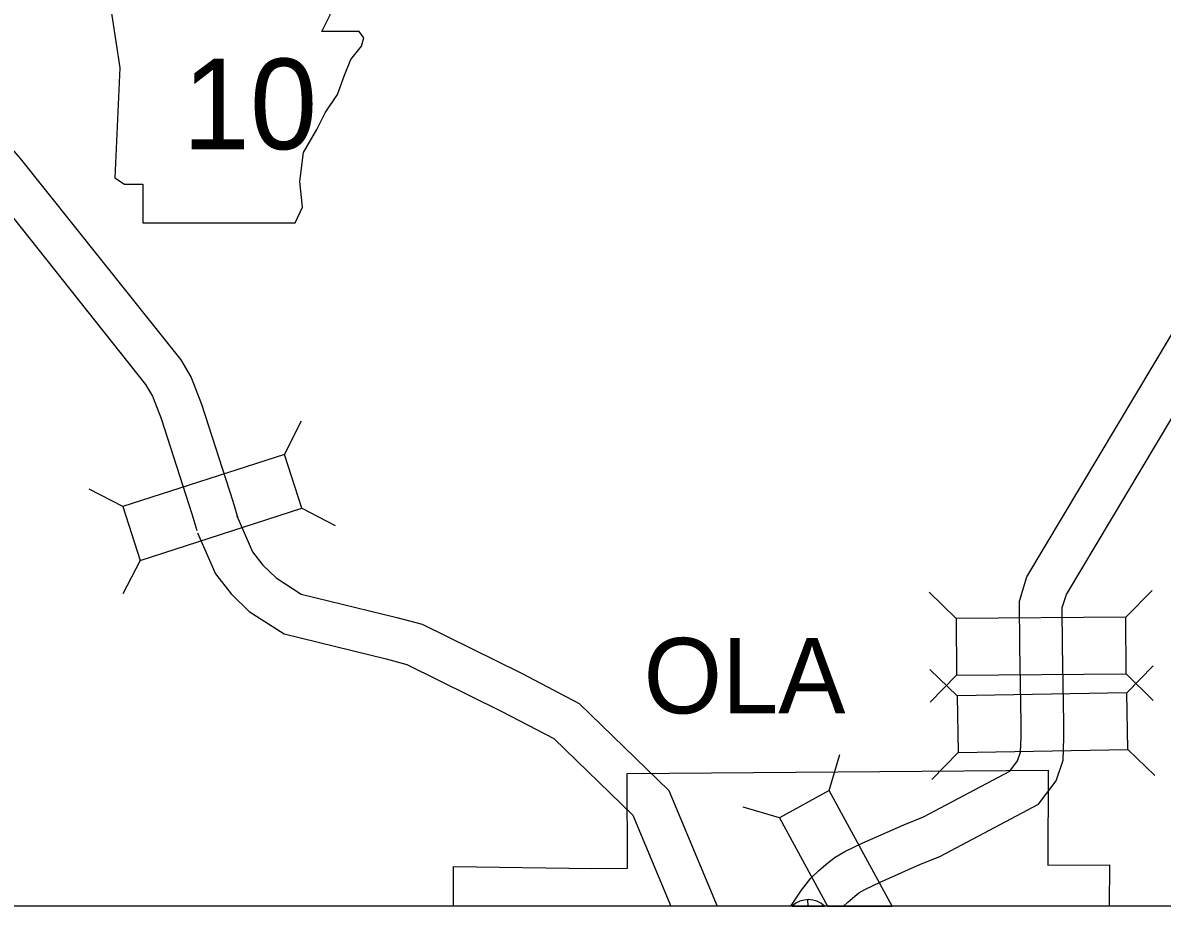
# Model space of a CAD drawing. Extents: x 1374139 to 1377472, y 1168351 to 1170484.
# Drawn here: x 1374355.8 to 1374435.6, y 1169604.3 to 1169666.1 of the extents above; entities that cross this region are included whole.
import ezdxf

# ---------------------------------------------------------------- set-up
doc = ezdxf.new("R2010")
doc.units = 0
doc.layers.add('26', color=7, linetype='Continuous')
doc.layers.add('Default', color=7, linetype='Continuous')

msp = doc.modelspace()

# ---------------------------------------------------------------- linework, layer by layer
at = {"layer": '26'}
msp.add_lwpolyline([(1374299.152, 1170388.771), (1375028.549, 1170388.771), (1375028.549, 1169604.285), (1374299.152, 1169604.285)], close=True, dxfattribs=at)
at = {"layer": 'Default'}
for p, q in [((1374374.148, 1169635.887), (1374375.352, 1169638.236)), ((1374362.84, 1169632.244), (1374360.491, 1169633.448)), ((1374375.362, 1169632.118), (1374377.712, 1169630.913)), ((1374364.055, 1169628.475), (1374362.85, 1169626.126)), ((1374421.143, 1169624.407), (1374419.263, 1169626.26)), ((1374433.023, 1169624.497), (1374434.876, 1169626.378)), ((1374433.095, 1169619.21), (1374434.93, 1169621.108)), ((1374421.217, 1169619.005), (1374419.318, 1169620.84)), ((1374421.173, 1169620.448), (1374419.321, 1169618.567)), ((1374433.053, 1169620.537), (1374434.934, 1169618.685)), ((1374412.26, 1169612.369), (1374413.005, 1169614.902)), ((1374421.285, 1169615.046), (1374419.451, 1169613.147)), ((1374433.163, 1169615.25), (1374435.062, 1169613.416)), ((1374398.137, 1169613.561), (1374427.592, 1169613.812)), ((1374427.592, 1169613.812), (1374427.573, 1169607.151)), ((1374398.164, 1169606.951), (1374398.137, 1169613.561)), ((1374412.26, 1169612.369), (1374408.784, 1169610.473)), ((1374416.67, 1169604.285), (1374412.26, 1169612.369)), ((1374408.784, 1169610.473), (1374406.251, 1169611.218)), ((1374408.784, 1169610.473), (1374412.159, 1169604.285)), ((1374385.975, 1169604.285), (1374385.973, 1169607.06)), ((1374385.973, 1169607.06), (1374395.653, 1169606.916)), ((1374395.653, 1169606.916), (1374398.164, 1169606.951)), ((1374427.573, 1169607.151), (1374431.884, 1169607.17)), ((1374431.884, 1169607.17), (1374431.86, 1169604.285)), ((1374431.86, 1169604.285), (1374385.975, 1169604.285)), ((1374409.68, 1169604.285), (1374411.945, 1169604.285)), ((1374410.786, 1169604.285), (1374410.775, 1169604.743)), ((1374412.159, 1169604.285), (1374416.67, 1169604.285))]:
    msp.add_line(p, q, dxfattribs=at)
for points in [[(1374361.873, 1169667.995), (1374362.634, 1169662.92), (1374362.296, 1169655.222), (1374362.973, 1169654.799), (1374364.242, 1169654.799), (1374364.242, 1169652.092), (1374374.9, 1169652.092), (1374375.407, 1169653.192), (1374375.238, 1169654.968), (1374375.492, 1169656.999), (1374376.422, 1169658.606), (1374377.015, 1169659.79), (1374377.86, 1169661.059), (1374378.368, 1169662.412), (1374378.791, 1169663.512), (1374379.552, 1169664.443), (1374379.721, 1169665.035), (1374379.383, 1169665.458), (1374376.761, 1169665.458), (1374377.353, 1169666.642), (1374377.437, 1169667.403), (1374377.087, 1169667.988)], [(1374374.148, 1169635.887), (1374362.84, 1169632.244), (1374364.055, 1169628.475), (1374375.362, 1169632.118)], [(1374433.023, 1169624.497), (1374421.143, 1169624.407), (1374421.173, 1169620.448), (1374433.053, 1169620.537)], [(1374433.095, 1169619.21), (1374421.217, 1169619.005), (1374421.285, 1169615.046), (1374433.163, 1169615.25)]]:
    msp.add_lwpolyline(points, close=True, dxfattribs=at)
for points in [[(1374299.152, 1169665.963), (1374309.667, 1169665.493), (1374321.244, 1169662.758), (1374324.312, 1169662.003), (1374325.25, 1169661.914), (1374326.212, 1169661.933), (1374338.959, 1169664.122), (1374341.94, 1169664.061), (1374344.169, 1169663.736), (1374346.452, 1169663.148), (1374348.446, 1169662.417), (1374350.336, 1169661.37), (1374351.802, 1169660.379), (1374354.035, 1169658.461), (1374355.675, 1169656.592), (1374366.895, 1169642.5), (1374367.635, 1169641.272), (1374368.352, 1169639.4), (1374370.534, 1169632.627), (1374370.891, 1169631.438)], [(1374299.152, 1169662.96), (1374309.251, 1169662.508), (1374320.541, 1169659.842), (1374323.809, 1169659.038), (1374325.137, 1169658.911), (1374326.497, 1169658.938), (1374339.185, 1169661.117), (1374341.691, 1169661.065), (1374343.577, 1169660.79), (1374345.56, 1169660.28), (1374347.196, 1169659.68), (1374348.766, 1169658.81), (1374349.979, 1169657.991), (1374351.92, 1169656.324), (1374353.373, 1169654.667), (1374364.427, 1169640.783), (1374364.929, 1169639.951), (1374365.521, 1169638.403), (1374367.669, 1169631.735), (1374368.019, 1169630.573)], [(1374418.862, 1169610.54), (1374424.905, 1169613.73), (1374425.449, 1169614.463), (1374425.649, 1169615.049), (1374425.695, 1169616.123), (1374425.69, 1169617.111), (1374425.598, 1169622.454), (1374425.574, 1169625.613), (1374426.104, 1169627.321), (1374438.712, 1169648.426)], [(1374420.001, 1169607.765), (1374426.92, 1169611.412), (1374428.137, 1169613.051), (1374428.628, 1169614.489), (1374428.696, 1169616.066), (1374428.69, 1169617.145), (1374428.598, 1169622.491), (1374428.578, 1169625.169), (1374428.863, 1169626.09), (1374441.458, 1169647.174)], [(1374370.831, 1169631.602), (1374371.927, 1169629.076), (1374372.654, 1169628.147), (1374373.571, 1169627.256), (1374375.328, 1169626.122), (1374382.011, 1169624.488), (1374383.78, 1169624.015), (1374390.734, 1169620.582), (1374394.772, 1169618.464), (1374401.05, 1169612.38), (1374404.437, 1169604.285)], [(1374368.079, 1169630.409), (1374369.328, 1169627.53), (1374370.418, 1169626.137), (1374371.694, 1169624.897), (1374374.125, 1169623.328), (1374381.267, 1169621.581), (1374382.719, 1169621.193), (1374389.373, 1169617.909), (1374392.995, 1169616.008), (1374398.52, 1169610.654), (1374401.185, 1169604.285)], [(1374409.586, 1169604.285), (1374410.322, 1169605.397), (1374410.994, 1169606.255), (1374411.539, 1169606.782), (1374412.168, 1169607.33), (1374412.684, 1169607.717), (1374413.357, 1169608.107), (1374414.574, 1169608.685), (1374417.485, 1169609.975), (1374418.862, 1169610.54)], [(1374413.273, 1169604.285), (1374413.57, 1169604.573), (1374414.057, 1169604.997), (1374414.341, 1169605.211), (1374414.755, 1169605.45), (1374415.825, 1169605.959), (1374418.662, 1169607.215), (1374420.001, 1169607.765)]]:
    msp.add_lwpolyline(points, dxfattribs=at)
msp.add_arc((1374410.813, 1169603.116), 1.628, 45.91449, 134.08551, dxfattribs=at)

# ---------------------------------------------------------------- texts
for s, height, p in [('10', 6.336, (1374367.027, 1169657.234)), ('OLA', 5.28, (1374399.283, 1169617.772))]:
    msp.add_text(s, height=height, dxfattribs=at).set_placement(p)

doc.saveas('drawing.dxf')
